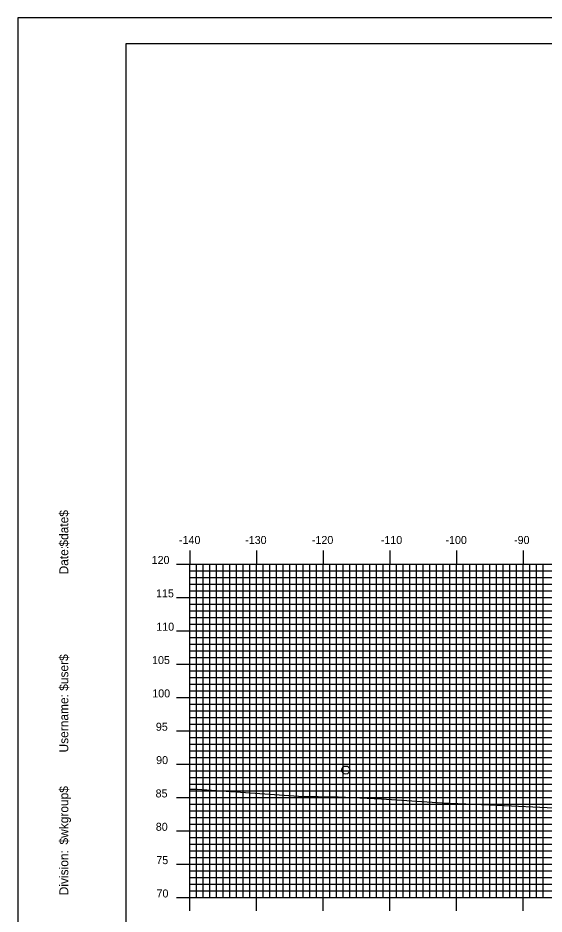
# Model space of a CAD drawing. Extents: x 857897 to 858240, y 364765 to 364985.
# Drawn here: x 857897 to 857976, y 364850.8 to 364985.2 of the extents above; entities that cross this region are included whole.
import ezdxf

# ---------------------------------------------------------------- set-up
doc = ezdxf.new("R2010")
doc.units = 0
for name, color, linetype in [('BORDER', 7, 'Continuous'), ('H_V ANNOTATION', 7, 'Continuous'), ('MAJOR', 7, 'Continuous'), ('MINOR', 7, 'Continuous'), ('PLOT BOUNDARY', 7, 'Continuous'), ('S_Drainage_Invert', 7, 'Continuous'), ('S_Roadway_Centerline', 7, 'Continuous')]:
    doc.layers.add(name, color=color, linetype=linetype)

msp = doc.modelspace()

# ---------------------------------------------------------------- linework, layer by layer
at = {"layer": 'BORDER'}
msp.add_lwpolyline([(857913.22, 364771.3), (858233.22, 364771.3), (858233.22, 364981.3), (857913.22, 364981.3)], close=True, dxfattribs=at)
at = {"layer": 'MAJOR'}
for p, q in [((857922.82, 364905.31), (857922.82, 364903.3)), ((857932.82, 364905.31), (857932.82, 364903.3)), ((857942.82, 364905.31), (857942.82, 364903.3)), ((857952.82, 364905.31), (857952.82, 364903.3)), ((857962.82, 364905.31), (857962.82, 364903.3)), ((857972.82, 364905.31), (857972.82, 364903.3)), ((857920.82, 364903.3), (857922.82, 364903.3)), ((857922.82, 364903.3), (858202.82, 364903.3)), ((857922.82, 364853.3), (857922.82, 364903.3)), ((857922.82, 364853.3), (857922.82, 364903.3)), ((857922.82, 364903.3), (858202.82, 364903.3)), ((857932.82, 364853.3), (857932.82, 364903.3)), ((857942.82, 364853.3), (857942.82, 364903.3)), ((857952.82, 364853.3), (857952.82, 364903.3)), ((857962.82, 364853.3), (857962.82, 364903.3)), ((857972.82, 364853.3), (857972.82, 364903.3)), ((857920.82, 364898.3), (857922.82, 364898.3)), ((857922.82, 364898.3), (858202.82, 364898.3)), ((857920.82, 364893.3), (857922.82, 364893.3)), ((857922.82, 364893.3), (858202.82, 364893.3)), ((857920.82, 364888.3), (857922.82, 364888.3)), ((857922.82, 364888.3), (858202.82, 364888.3)), ((857920.82, 364883.3), (857922.82, 364883.3)), ((857922.82, 364883.3), (858202.82, 364883.3)), ((857920.82, 364878.3), (857922.82, 364878.3)), ((857922.82, 364878.3), (858202.82, 364878.3)), ((857920.82, 364873.3), (857922.82, 364873.3)), ((857922.82, 364873.3), (858202.82, 364873.3)), ((857920.82, 364868.3), (857922.82, 364868.3)), ((857922.82, 364868.3), (858202.82, 364868.3)), ((857920.82, 364863.3), (857922.82, 364863.3)), ((857922.82, 364863.3), (858202.82, 364863.3)), ((857920.82, 364858.3), (857922.82, 364858.3)), ((857922.82, 364858.3), (858202.82, 364858.3)), ((857920.82, 364853.3), (857922.82, 364853.3)), ((857922.82, 364853.3), (858202.82, 364853.3)), ((857922.82, 364853.3), (858202.82, 364853.3)), ((857922.82, 364851.3), (857922.82, 364853.3)), ((857932.82, 364851.3), (857932.82, 364853.3)), ((857942.82, 364851.3), (857942.82, 364853.3)), ((857952.82, 364851.3), (857952.82, 364853.3)), ((857962.82, 364851.3), (857962.82, 364853.3)), ((857972.82, 364851.3), (857972.82, 364853.3))]:
    msp.add_line(p, q, dxfattribs=at)
at = {"layer": 'MINOR'}
for p, q in [((857923.82, 364853.3), (857923.82, 364903.3)), ((857924.82, 364853.3), (857924.82, 364903.3)), ((857925.82, 364853.3), (857925.82, 364903.3)), ((857926.82, 364853.3), (857926.82, 364903.3)), ((857927.82, 364853.3), (857927.82, 364903.3)), ((857928.82, 364853.3), (857928.82, 364903.3)), ((857929.82, 364853.3), (857929.82, 364903.3)), ((857930.82, 364853.3), (857930.82, 364903.3)), ((857931.82, 364853.3), (857931.82, 364903.3)), ((857933.82, 364853.3), (857933.82, 364903.3)), ((857934.82, 364853.3), (857934.82, 364903.3)), ((857935.82, 364853.3), (857935.82, 364903.3)), ((857936.82, 364853.3), (857936.82, 364903.3)), ((857937.82, 364853.3), (857937.82, 364903.3)), ((857938.82, 364853.3), (857938.82, 364903.3)), ((857939.82, 364853.3), (857939.82, 364903.3)), ((857940.82, 364853.3), (857940.82, 364903.3)), ((857941.82, 364853.3), (857941.82, 364903.3)), ((857943.82, 364853.3), (857943.82, 364903.3)), ((857944.82, 364853.3), (857944.82, 364903.3)), ((857945.82, 364853.3), (857945.82, 364903.3)), ((857946.82, 364853.3), (857946.82, 364903.3)), ((857947.82, 364853.3), (857947.82, 364903.3)), ((857948.82, 364853.3), (857948.82, 364903.3)), ((857949.82, 364853.3), (857949.82, 364903.3)), ((857950.82, 364853.3), (857950.82, 364903.3)), ((857951.82, 364853.3), (857951.82, 364903.3)), ((857953.82, 364853.3), (857953.82, 364903.3)), ((857954.82, 364853.3), (857954.82, 364903.3)), ((857955.82, 364853.3), (857955.82, 364903.3)), ((857956.82, 364853.3), (857956.82, 364903.3)), ((857957.82, 364853.3), (857957.82, 364903.3)), ((857958.82, 364853.3), (857958.82, 364903.3)), ((857959.82, 364853.3), (857959.82, 364903.3)), ((857960.82, 364853.3), (857960.82, 364903.3)), ((857961.82, 364853.3), (857961.82, 364903.3)), ((857963.82, 364853.3), (857963.82, 364903.3)), ((857964.82, 364853.3), (857964.82, 364903.3)), ((857965.82, 364853.3), (857965.82, 364903.3)), ((857966.82, 364853.3), (857966.82, 364903.3)), ((857967.82, 364853.3), (857967.82, 364903.3)), ((857968.82, 364853.3), (857968.82, 364903.3)), ((857969.82, 364853.3), (857969.82, 364903.3)), ((857970.82, 364853.3), (857970.82, 364903.3)), ((857971.82, 364853.3), (857971.82, 364903.3)), ((857973.82, 364853.3), (857973.82, 364903.3)), ((857974.82, 364853.3), (857974.82, 364903.3)), ((857975.82, 364853.3), (857975.82, 364903.3)), ((857922.82, 364902.3), (858202.82, 364902.3)), ((857922.82, 364902.3), (857924.82, 364902.3)), ((857922.82, 364901.3), (858202.82, 364901.3)), ((857922.82, 364901.3), (857924.82, 364901.3)), ((857922.82, 364900.3), (858202.82, 364900.3)), ((857922.82, 364900.3), (857924.82, 364900.3)), ((857922.82, 364899.3), (858202.82, 364899.3)), ((857922.82, 364899.3), (857924.82, 364899.3)), ((857922.82, 364897.3), (858202.82, 364897.3)), ((857922.82, 364897.3), (857924.82, 364897.3)), ((857922.82, 364896.3), (858202.82, 364896.3)), ((857922.82, 364896.3), (857924.82, 364896.3)), ((857922.82, 364895.3), (858202.82, 364895.3)), ((857922.82, 364895.3), (857924.82, 364895.3)), ((857922.82, 364894.3), (858202.82, 364894.3)), ((857922.82, 364894.3), (857924.82, 364894.3)), ((857922.82, 364892.3), (858202.82, 364892.3)), ((857922.82, 364892.3), (857924.82, 364892.3)), ((857922.82, 364891.3), (858202.82, 364891.3)), ((857922.82, 364891.3), (857924.82, 364891.3)), ((857922.82, 364890.3), (858202.82, 364890.3)), ((857922.82, 364890.3), (857924.82, 364890.3)), ((857922.82, 364889.3), (858202.82, 364889.3)), ((857922.82, 364889.3), (857924.82, 364889.3)), ((857922.82, 364887.3), (858202.82, 364887.3)), ((857922.82, 364887.3), (857924.82, 364887.3)), ((857922.82, 364886.3), (858202.82, 364886.3)), ((857922.82, 364886.3), (857924.82, 364886.3)), ((857922.82, 364885.3), (858202.82, 364885.3)), ((857922.82, 364885.3), (857924.82, 364885.3)), ((857922.82, 364884.3), (858202.82, 364884.3)), ((857922.82, 364884.3), (857924.82, 364884.3)), ((857922.82, 364882.3), (858202.82, 364882.3)), ((857922.82, 364882.3), (857924.82, 364882.3)), ((857922.82, 364881.3), (858202.82, 364881.3)), ((857922.82, 364881.3), (857924.82, 364881.3)), ((857922.82, 364880.3), (858202.82, 364880.3)), ((857922.82, 364880.3), (857924.82, 364880.3)), ((857922.82, 364879.3), (858202.82, 364879.3)), ((857922.82, 364879.3), (857924.82, 364879.3)), ((857922.82, 364877.3), (858202.82, 364877.3)), ((857922.82, 364877.3), (857924.82, 364877.3)), ((857922.82, 364876.3), (858202.82, 364876.3)), ((857922.82, 364876.3), (857924.82, 364876.3)), ((857922.82, 364875.3), (858202.82, 364875.3)), ((857922.82, 364875.3), (857924.82, 364875.3)), ((857922.82, 364874.3), (858202.82, 364874.3)), ((857922.82, 364874.3), (857924.82, 364874.3)), ((857922.82, 364872.3), (858202.82, 364872.3)), ((857922.82, 364872.3), (857924.82, 364872.3)), ((857922.82, 364871.3), (858202.82, 364871.3)), ((857922.82, 364871.3), (857924.82, 364871.3)), ((857922.82, 364870.3), (858202.82, 364870.3)), ((857922.82, 364870.3), (857924.82, 364870.3)), ((857922.82, 364869.3), (858202.82, 364869.3)), ((857922.82, 364869.3), (857924.82, 364869.3)), ((857922.82, 364867.3), (858202.82, 364867.3)), ((857922.82, 364867.3), (857924.82, 364867.3)), ((857922.82, 364866.3), (858202.82, 364866.3)), ((857922.82, 364866.3), (857924.82, 364866.3)), ((857922.82, 364865.3), (858202.82, 364865.3)), ((857922.82, 364865.3), (857924.82, 364865.3)), ((857922.82, 364864.3), (858202.82, 364864.3)), ((857922.82, 364864.3), (857924.82, 364864.3)), ((857922.82, 364862.3), (858202.82, 364862.3)), ((857922.82, 364862.3), (857924.82, 364862.3)), ((857922.82, 364861.3), (858202.82, 364861.3)), ((857922.82, 364861.3), (857924.82, 364861.3)), ((857922.82, 364860.3), (858202.82, 364860.3)), ((857922.82, 364860.3), (857924.82, 364860.3)), ((857922.82, 364859.3), (858202.82, 364859.3)), ((857922.82, 364859.3), (857924.82, 364859.3)), ((857922.82, 364857.3), (858202.82, 364857.3)), ((857922.82, 364857.3), (857924.82, 364857.3)), ((857922.82, 364856.3), (858202.82, 364856.3)), ((857922.82, 364856.3), (857924.82, 364856.3)), ((857922.82, 364855.3), (858202.82, 364855.3)), ((857922.82, 364855.3), (857924.82, 364855.3)), ((857922.82, 364854.3), (858202.82, 364854.3)), ((857922.82, 364854.3), (857924.82, 364854.3))]:
    msp.add_line(p, q, dxfattribs=at)
at = {"layer": 'PLOT BOUNDARY'}
msp.add_lwpolyline([(857897.03, 364765.18), (858237.03, 364765.18), (858237.03, 364985.18), (857897.03, 364985.18)], close=True, dxfattribs=at)
at = {"layer": 'S_Drainage_Invert'}
msp.add_circle((857946.23, 364872.41), 0.6, dxfattribs=at)
at = {"layer": 'S_Roadway_Centerline'}
msp.add_lwpolyline([(857922.82, 364869.53), (857923.95, 364869.52), (857939.13, 364868.49), (857945.1, 364868.38), (857951.57, 364868.07), (857960.69, 364867.5), (857968.94, 364867.12), (857977.46, 364866.75), (857989.04, 364866.25), (858001.2, 364865.69), (858006.87, 364865.36), (858013.81, 364865.2), (858033.57, 364864.37), (858043.41, 364863.75), (858045.08, 364863.5), (858047.56, 364863.36), (858059.78, 364862.66), (858066.49, 364862.17), (858070.62, 364862.03), (858082.49, 364860.71)], dxfattribs=at)

# ---------------------------------------------------------------- texts
at = {"layer": 'BORDER'}
for s, p in [('$date$', (857904.59, 364905.91)), ('Date:', (857904.59, 364901.74)), ('$user$', (857904.59, 364884.29)), ('Username:', (857904.59, 364875.04)), ('$wkgroup$', (857904.59, 364861.24)), ('Division:', (857904.59, 364853.63))]:
    msp.add_text(s, height=1.339, rotation=90, dxfattribs=at).set_placement(p)
at = {"layer": 'H_V ANNOTATION'}
for s, p in [('-140', (857921.2, 364906.3)), ('-130', (857931.13, 364906.3)), ('-120', (857941.14, 364906.3)), ('-110', (857951.48, 364906.3)), ('-100', (857961.18, 364906.3)), ('-90', (857971.47, 364906.3)), ('120', (857917.1, 364903.3)), ('115', (857917.76, 364898.3)), ('110', (857917.79, 364893.3)), ('105', (857917.16, 364888.3)), ('100', (857917.19, 364883.3)), ('95', (857917.73, 364878.3)), ('90', (857917.77, 364873.3)), ('85', (857917.69, 364868.3)), ('80', (857917.72, 364863.3)), ('75', (857917.8, 364858.3)), ('70', (857917.83, 364853.3))]:
    msp.add_text(s, height=1.2, dxfattribs=at).set_placement(p)
at = {"layer": 'MAJOR'}
msp.add_text('-', height=0.012, dxfattribs=at).set_placement((857922.81, 364853.3))

doc.saveas('drawing.dxf')
